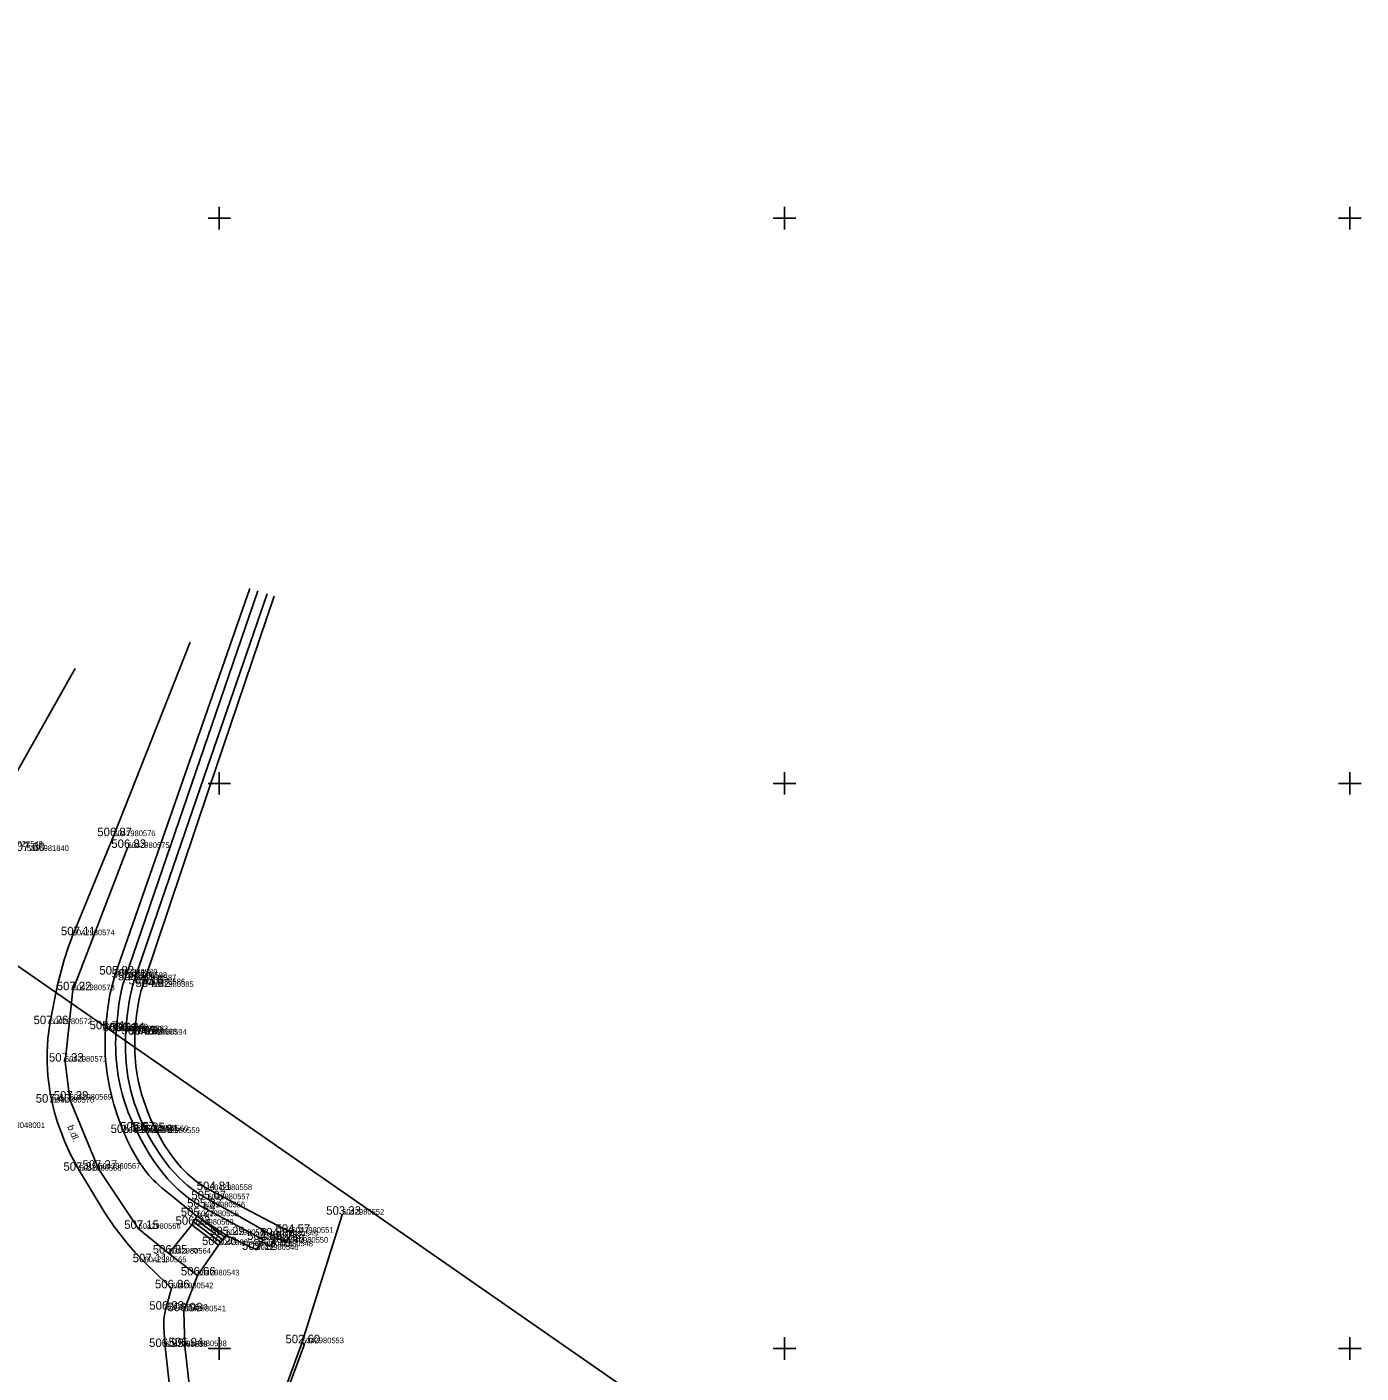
# Model space of a CAD drawing. Extents: x -669251 to -668549, y -1128351 to -1127698.
# Drawn here: x -668667 to -668549, y -1127952.2 to -1127833.1 of the extents above; entities that cross this region are included whole.
import ezdxf

# ---------------------------------------------------------------- set-up
doc = ezdxf.new("R2010")
doc.units = 0
for name, color, linetype in [('Vrstva 1', 7, 'Continuous'), ('Vrstva 10', 7, 'Continuous'), ('Vrstva 11', 7, 'Continuous'), ('Vrstva 2', 7, 'Continuous'), ('Vrstva 3', 7, 'Continuous'), ('Vrstva 40', 7, 'Continuous'), ('Vrstva 60', 7, 'Continuous'), ('Vrstva 61', 7, 'Continuous'), ('Vrstva 7', 7, 'Continuous'), ('Vrstva 9', 7, 'Continuous')]:
    doc.layers.add(name, color=color, linetype=linetype)

msp = doc.modelspace()

# ---------------------------------------------------------------- linework, layer by layer
at = {"layer": 'Vrstva 1'}
for p, q in [((-668659.36, -1127904.67), (-668659.36, -1127904.67)), ((-668658.12, -1127905.71), (-668658.12, -1127905.71)), ((-668662.97, -1127913.44), (-668662.97, -1127913.44)), ((-668659.2, -1127916.91), (-668659.2, -1127916.91)), ((-668658.34, -1127917.22), (-668658.34, -1127917.22)), ((-668657.52, -1127917.43), (-668657.52, -1127917.43)), ((-668656.74, -1127917.78), (-668656.74, -1127917.78)), ((-668655.99, -1127918.02), (-668655.99, -1127918.02)), ((-668662.97, -1127918.3), (-668662.97, -1127918.3)), ((-668664.99, -1127921.3), (-668664.99, -1127921.3)), ((-668660.06, -1127921.76), (-668660.06, -1127921.76)), ((-668659.12, -1127921.93), (-668659.12, -1127921.93)), ((-668658.26, -1127921.93), (-668658.26, -1127921.93)), ((-668657.46, -1127922.21), (-668657.46, -1127922.21)), ((-668656.6, -1127922.24), (-668656.6, -1127922.24)), ((-668663.65, -1127924.62), (-668663.65, -1127924.62)), ((-668664.79, -1127928.24), (-668664.79, -1127928.24)), ((-668663.23, -1127927.98), (-668663.23, -1127927.98)), ((-668658.42, -1127930.93), (-668658.42, -1127930.93)), ((-668657.34, -1127930.71), (-668657.34, -1127930.71)), ((-668656.47, -1127930.77), (-668656.47, -1127930.77)), ((-668655.45, -1127930.94), (-668655.45, -1127930.94)), ((-668662.37, -1127934.27), (-668662.37, -1127934.27)), ((-668660.7, -1127934.09), (-668660.7, -1127934.09)), ((-668651.03, -1127936.79), (-668651.03, -1127936.79)), ((-668650.82, -1127935.98), (-668650.82, -1127935.98)), ((-668651.43, -1127937.51), (-668651.43, -1127937.51)), ((-668639.13, -1127938.16), (-668639.13, -1127938.16)), ((-668657.14, -1127939.41), (-668657.14, -1127939.41)), ((-668652.44, -1127939.05), (-668652.44, -1127939.05)), ((-668651.99, -1127938.29), (-668651.99, -1127938.29)), ((-668649.4, -1127939.96), (-668649.4, -1127939.96)), ((-668646.12, -1127940.39), (-668646.12, -1127940.39)), ((-668644.99, -1127940.08), (-668644.99, -1127940.08)), ((-668644.08, -1127940.64), (-668644.08, -1127940.64)), ((-668643.61, -1127939.76), (-668643.61, -1127939.76)), ((-668654.46, -1127941.6), (-668654.46, -1127941.6)), ((-668650.07, -1127940.85), (-668650.07, -1127940.85)), ((-668646.72, -1127941.27), (-668646.72, -1127941.27)), ((-668645.43, -1127940.96), (-668645.43, -1127940.96)), ((-668656.62, -1127942.36), (-668656.62, -1127942.36)), ((-668651.94, -1127943.53), (-668651.94, -1127943.53)), ((-668654.24, -1127944.67), (-668654.24, -1127944.67)), ((-668654.76, -1127946.56), (-668654.76, -1127946.56)), ((-668653.13, -1127946.7), (-668653.13, -1127946.7)), ((-668654.78, -1127949.86), (-668654.78, -1127949.86)), ((-668653.06, -1127949.79), (-668653.06, -1127949.79)), ((-668642.69, -1127949.53), (-668642.69, -1127949.53))]:
    msp.add_line(p, q, dxfattribs=at)
at = {"layer": 'Vrstva 10'}
for p, q in [((-668662.74, -1127889.83), (-668682.21, -1127924.28)), ((-668651.94, -1127943.53), (-668654.46, -1127941.6)), ((-668645.91, -1127958.22), (-668642.69, -1127949.53)), ((-668645.66, -1127958.2), (-668642.45, -1127949.61)), ((-668642.69, -1127949.53), (-668642.45, -1127949.61))]:
    msp.add_line(p, q, dxfattribs=at)
for points in [[(-668654.24, -1127944.67), (-668655.43, -1127943.52), (-668656.62, -1127942.36), (-668657.48, -1127941.48), (-668658.19, -1127940.66), (-668659.33, -1127939.16), (-668660.13, -1127937.98), (-668661.26, -1127936.15), (-668662.37, -1127934.27), (-668663.16, -1127932.82), (-668663.67, -1127931.71), (-668664.3, -1127930.01), (-668664.57, -1127929.13), (-668664.79, -1127928.24), (-668664.96, -1127927.39), (-668665.17, -1127925.86), (-668665.24, -1127924.72), (-668665.24, -1127923.85), (-668665.17, -1127922.57), (-668664.99, -1127921.3), (-668664.62, -1127919.31), (-668664.3, -1127917.81), (-668663.72, -1127915.6), (-668663.37, -1127914.51), (-668662.97, -1127913.44), (-668661.16, -1127909.05), (-668659.36, -1127904.67), (-668655.98, -1127896.08), (-668652.59, -1127887.5)], [(-668651.54, -1127974.65), (-668652.61, -1127967.03), (-668653.68, -1127959.4), (-668654.27, -1127954.63), (-668654.78, -1127949.86), (-668654.92, -1127948.2), (-668654.9, -1127947.37), (-668654.76, -1127946.56), (-668654.5, -1127945.62), (-668654.24, -1127944.67)]]:
    msp.add_lwpolyline(points, dxfattribs=at)
at = {"layer": 'Vrstva 11'}
for p, q in [((-668652.44, -1127939.05), (-668650.07, -1127940.85)), ((-668652.28, -1127938.79), (-668649.9, -1127940.6)), ((-668652.13, -1127938.53), (-668649.73, -1127940.35)), ((-668651.99, -1127938.29), (-668651.76, -1127938.44)), ((-668651.76, -1127938.44), (-668649.56, -1127940.11)), ((-668651.76, -1127938.44), (-668649.4, -1127939.96))]:
    msp.add_line(p, q, dxfattribs=at)
at = {"layer": 'Vrstva 60'}
msp.add_lwpolyline([(-668788.58, -1128325.45), (-668557.46, -1127992.87), (-668787.38, -1127833.08), (-669018.51, -1128165.66)], close=True, dxfattribs=at)
at = {"layer": 'Vrstva 61'}
for p, q in [((-668651, -1127850), (-668649, -1127850)), ((-668650, -1127849), (-668650, -1127851)), ((-668601, -1127850), (-668599, -1127850)), ((-668600, -1127849), (-668600, -1127851)), ((-668551, -1127850), (-668549, -1127850)), ((-668550, -1127849), (-668550, -1127851)), ((-668651, -1127900), (-668649, -1127900)), ((-668650, -1127899), (-668650, -1127901)), ((-668601, -1127900), (-668599, -1127900)), ((-668600, -1127899), (-668600, -1127901)), ((-668551, -1127900), (-668549, -1127900)), ((-668550, -1127899), (-668550, -1127901)), ((-668651, -1127950), (-668649, -1127950)), ((-668650, -1127949), (-668650, -1127951)), ((-668601, -1127950), (-668599, -1127950)), ((-668600, -1127949), (-668600, -1127951)), ((-668551, -1127950), (-668549, -1127950)), ((-668550, -1127949), (-668550, -1127951))]:
    msp.add_line(p, q, dxfattribs=at)
at = {"layer": 'Vrstva 7'}
for p, q in [((-668642.69, -1127949.53), (-668639.13, -1127938.16)), ((-668646.72, -1127941.27), (-668649.4, -1127939.96)), ((-668646.24, -1127940.56), (-668646.72, -1127941.27)), ((-668646.12, -1127940.39), (-668646.24, -1127940.56)), ((-668646.24, -1127940.56), (-668645.43, -1127940.96)), ((-668645.43, -1127940.96), (-668645.02, -1127940.14)), ((-668645.02, -1127940.14), (-668644.08, -1127940.64)), ((-668643.61, -1127939.76), (-668644.08, -1127940.64))]:
    msp.add_line(p, q, dxfattribs=at)
for points in [[(-668651.99, -1127938.29), (-668653.53, -1127937.04), (-668655.07, -1127935.79), (-668655.35, -1127935.55), (-668655.6, -1127935.32), (-668655.83, -1127935.09), (-668656.23, -1127934.65), (-668656.56, -1127934.24), (-668656.83, -1127933.87), (-668657.06, -1127933.54), (-668657.25, -1127933.24), (-668657.57, -1127932.69), (-668657.79, -1127932.27), (-668658.11, -1127931.61), (-668658.42, -1127930.93), (-668658.65, -1127930.36), (-668658.86, -1127929.82), (-668659.04, -1127929.32), (-668659.19, -1127928.85), (-668659.33, -1127928.4), (-668659.55, -1127927.57), (-668659.72, -1127926.85), (-668659.84, -1127926.21), (-668659.93, -1127925.66), (-668659.99, -1127925.17), (-668660.04, -1127924.74), (-668660.09, -1127924), (-668660.11, -1127923.44), (-668660.1, -1127922.6), (-668660.09, -1127922.18), (-668660.06, -1127921.76), (-668660.01, -1127921.15), (-668659.89, -1127920.08), (-668659.78, -1127919.28), (-668659.67, -1127918.67), (-668659.57, -1127918.23), (-668659.4, -1127917.56), (-668659.2, -1127916.91), (-668653.26, -1127899.83), (-668647.31, -1127882.76)], [(-668646.6, -1127882.98), (-668652.47, -1127900.1), (-668658.34, -1127917.22), (-668658.52, -1127917.79), (-668658.65, -1127918.3), (-668658.74, -1127918.75), (-668658.88, -1127919.54), (-668658.96, -1127920.14), (-668659.05, -1127921.04), (-668659.12, -1127921.93), (-668659.15, -1127922.49), (-668659.17, -1127923), (-668659.16, -1127923.49), (-668659.15, -1127923.94), (-668659.12, -1127924.36), (-668659.04, -1127925.16), (-668658.94, -1127925.86), (-668658.83, -1127926.47), (-668658.71, -1127927), (-668658.59, -1127927.46), (-668658.47, -1127927.87), (-668658.24, -1127928.58), (-668658.05, -1127929.11), (-668657.89, -1127929.51), (-668657.63, -1127930.11), (-668657.34, -1127930.71), (-668657.07, -1127931.26), (-668656.8, -1127931.75), (-668656.54, -1127932.21), (-668656.29, -1127932.63), (-668656.05, -1127933.01), (-668655.82, -1127933.36), (-668655.36, -1127934), (-668654.95, -1127934.53), (-668654.57, -1127934.98), (-668654.22, -1127935.35), (-668653.91, -1127935.67), (-668653.63, -1127935.94), (-668653.12, -1127936.38), (-668652.72, -1127936.69), (-668652.41, -1127936.91), (-668651.93, -1127937.22), (-668651.43, -1127937.51), (-668648.77, -1127938.95), (-668646.12, -1127940.39)], [(-668645.02, -1127940.14), (-668648.01, -1127938.43), (-668651.03, -1127936.79), (-668651.47, -1127936.53), (-668651.87, -1127936.28), (-668652.23, -1127936.03), (-668652.55, -1127935.78), (-668652.85, -1127935.54), (-668653.12, -1127935.3), (-668653.62, -1127934.83), (-668654.03, -1127934.4), (-668654.38, -1127934), (-668654.67, -1127933.64), (-668654.92, -1127933.31), (-668655.33, -1127932.72), (-668655.63, -1127932.25), (-668655.85, -1127931.89), (-668656.17, -1127931.34), (-668656.47, -1127930.77), (-668656.74, -1127930.22), (-668656.97, -1127929.7), (-668657.17, -1127929.22), (-668657.34, -1127928.76), (-668657.49, -1127928.34), (-668657.61, -1127927.94), (-668657.82, -1127927.19), (-668657.97, -1127926.53), (-668658.08, -1127925.96), (-668658.15, -1127925.46), (-668658.21, -1127925.02), (-668658.27, -1127924.24), (-668658.3, -1127923.67), (-668658.3, -1127923.23), (-668658.29, -1127922.58), (-668658.26, -1127921.93), (-668658.17, -1127920.79), (-668658.07, -1127919.94), (-668657.98, -1127919.3), (-668657.89, -1127918.82), (-668657.81, -1127918.47), (-668657.68, -1127917.94), (-668657.52, -1127917.43), (-668651.65, -1127900.33), (-668645.78, -1127883.22)], [(-668645.16, -1127883.44), (-668650.95, -1127900.61), (-668656.74, -1127917.78), (-668656.91, -1127918.32), (-668657.03, -1127918.79), (-668657.12, -1127919.22), (-668657.24, -1127919.96), (-668657.32, -1127920.53), (-668657.4, -1127921.37), (-668657.46, -1127922.21), (-668657.48, -1127922.76), (-668657.48, -1127923.28), (-668657.47, -1127923.76), (-668657.45, -1127924.22), (-668657.41, -1127924.64), (-668657.37, -1127925.03), (-668657.26, -1127925.78), (-668657.14, -1127926.43), (-668657.01, -1127926.99), (-668656.87, -1127927.49), (-668656.74, -1127927.92), (-668656.48, -1127928.68), (-668656.26, -1127929.24), (-668656.08, -1127929.67), (-668655.78, -1127930.3), (-668655.45, -1127930.94), (-668655.23, -1127931.34), (-668655.02, -1127931.72), (-668654.81, -1127932.06), (-668654.4, -1127932.67), (-668654.03, -1127933.19), (-668653.69, -1127933.61), (-668653.38, -1127933.97), (-668653.09, -1127934.27), (-668652.84, -1127934.52), (-668652.61, -1127934.73), (-668652.2, -1127935.08), (-668651.87, -1127935.33), (-668651.62, -1127935.5), (-668651.23, -1127935.75), (-668650.82, -1127935.98), (-668647.22, -1127937.87), (-668643.61, -1127939.76)]]:
    msp.add_lwpolyline(points, dxfattribs=at)
at = {"layer": 'Vrstva 9'}
for p, q in [((-668662.97, -1127918.3), (-668658.12, -1127905.71)), ((-668663.65, -1127924.62), (-668662.97, -1127918.3)), ((-668663.23, -1127927.98), (-668663.65, -1127924.62)), ((-668660.7, -1127934.09), (-668663.23, -1127927.98)), ((-668657.14, -1127939.41), (-668660.7, -1127934.09)), ((-668654.46, -1127941.6), (-668657.14, -1127939.41)), ((-668654.46, -1127941.6), (-668652.44, -1127939.05)), ((-668652.44, -1127939.05), (-668651.99, -1127938.29)), ((-668649.4, -1127939.96), (-668650.07, -1127940.85)), ((-668650.07, -1127940.85), (-668651.94, -1127943.53)), ((-668653.13, -1127946.7), (-668651.94, -1127943.53)), ((-668653.06, -1127949.79), (-668653.13, -1127946.7)), ((-668652.65, -1127953.43), (-668653.06, -1127949.79))]:
    msp.add_line(p, q, dxfattribs=at)

# ---------------------------------------------------------------- texts
at = {"layer": 'Vrstva 2'}
for s, p in [('6042980576', (-668659.36, -1127904.67)), ('7851022549', (-668669.33, -1127905.6)), ('5866981840', (-668667.03, -1127905.98)), ('6042980575', (-668658.12, -1127905.71)), ('6042980574', (-668662.97, -1127913.44)), ('6042980589', (-668659.2, -1127916.91)), ('6042980588', (-668658.34, -1127917.22)), ('6042980573', (-668662.97, -1127918.3)), ('6042980587', (-668657.52, -1127917.43)), ('6042980586', (-668656.74, -1127917.78)), ('6042980585', (-668655.99, -1127918.02)), ('6042980572', (-668664.99, -1127921.3)), ('6042980590', (-668660.06, -1127921.76)), ('6042980591', (-668659.12, -1127921.93)), ('6042980592', (-668658.26, -1127921.93)), ('6042980593', (-668657.46, -1127922.21)), ('6042980594', (-668656.6, -1127922.24)), ('6042980571', (-668663.65, -1127924.62)), ('6042980569', (-668663.23, -1127927.98)), ('6042980570', (-668664.79, -1127928.24)), ('6043048001', (-668669.14, -1127930.49)), ('6042980562', (-668658.42, -1127930.93)), ('6042980561', (-668657.34, -1127930.71)), ('6042980560', (-668656.47, -1127930.77)), ('6042980559', (-668655.45, -1127930.94)), ('6042980568', (-668662.37, -1127934.27)), ('6042980567', (-668660.7, -1127934.09)), ('6042980558', (-668650.82, -1127935.98)), ('6042980556', (-668651.43, -1127937.51)), ('6042980557', (-668651.03, -1127936.79)), ('6042980555', (-668651.99, -1127938.29)), ('6042980552', (-668639.13, -1127938.16)), ('6042980566', (-668657.14, -1127939.41)), ('6042980563', (-668652.44, -1127939.05)), ('6042980545', (-668649.4, -1127939.96)), ('6042980551', (-668643.61, -1127939.76)), ('6042980544', (-668650.07, -1127940.85)), ('6042980547', (-668646.12, -1127940.39)), ('6042980548', (-668645.43, -1127940.96)), ('6042980549', (-668644.99, -1127940.08)), ('6042980550', (-668644.08, -1127940.64)), ('6042980564', (-668654.46, -1127941.6)), ('6042980546', (-668646.72, -1127941.27)), ('6042980565', (-668656.62, -1127942.36)), ('6042980543', (-668651.94, -1127943.53)), ('6042980542', (-668654.24, -1127944.67)), ('6042980540', (-668654.76, -1127946.56)), ('6042980541', (-668653.13, -1127946.7)), ('6042980539', (-668654.78, -1127949.86)), ('6042980538', (-668653.06, -1127949.79)), ('6042980553', (-668642.69, -1127949.53))]:
    msp.add_text(s, height=0.5, dxfattribs=at).set_placement(p)
at = {"layer": 'Vrstva 3'}
for s, p in [('506.87 ', (-668660.79, -1127904.67)), ('507.60 ', (-668668.5, -1127905.98)), ('506.83 ', (-668659.55, -1127905.71)), ('507.11 ', (-668664.01, -1127913.44)), ('505.82 ', (-668660.61, -1127916.91)), ('505.81 ', (-668659.52, -1127917.22)), ('505.50 ', (-668658.97, -1127917.43)), ('507.22 ', (-668664.38, -1127918.3)), ('505.16 ', (-668658.04, -1127917.78)), ('504.82 ', (-668657.41, -1127918.02)), ('507.26 ', (-668666.43, -1127921.3)), ('505.74 ', (-668661.47, -1127921.76)), ('505.61 ', (-668660.32, -1127921.93)), ('505.34 ', (-668659.67, -1127921.93)), ('505.01 ', (-668658.66, -1127922.21)), ('504.70 ', (-668658.05, -1127922.24)), ('507.33 ', (-668665.07, -1127924.62)), ('507.40 ', (-668666.24, -1127928.24)), ('507.39 ', (-668664.65, -1127927.98)), ('505.61 ', (-668659.61, -1127930.93)), ('505.57 ', (-668658.76, -1127930.71)), ('505.25 ', (-668657.89, -1127930.77)), ('504.91 ', (-668656.64, -1127930.94)), ('507.39 ', (-668663.79, -1127934.27)), ('507.37 ', (-668662.11, -1127934.09)), ('504.81 ', (-668652, -1127935.98)), ('505.37 ', (-668652.84, -1127937.51)), ('505.07 ', (-668652.47, -1127936.79)), ('505.27 ', (-668653.41, -1127938.29)), ('503.33 ', (-668640.54, -1127938.16)), ('507.15 ', (-668658.41, -1127939.41)), ('506.23 ', (-668653.87, -1127939.05)), ('505.29 ', (-668650.82, -1127939.96)), ('504.88 ', (-668646.41, -1127940.08)), ('504.57 ', (-668645.03, -1127939.76)), ('506.20 ', (-668651.53, -1127940.85)), ('505.12 ', (-668647.99, -1127941.27)), ('504.89 ', (-668647.54, -1127940.39)), ('504.81 ', (-668646.61, -1127940.96)), ('504.46 ', (-668645.52, -1127940.64)), ('507.11 ', (-668657.66, -1127942.36)), ('506.85 ', (-668655.89, -1127941.6)), ('506.66 ', (-668653.4, -1127943.53)), ('506.86 ', (-668655.69, -1127944.67)), ('506.93 ', (-668656.19, -1127946.56)), ('506.96 ', (-668654.59, -1127946.7)), ('502.60 ', (-668644.15, -1127949.53)), ('506.99 ', (-668656.21, -1127949.86)), ('506.94 ', (-668654.49, -1127949.79))]:
    msp.add_text(s, height=0.75, dxfattribs=at).set_placement(p)
at = {"layer": 'Vrstva 40'}
for s, rotation, p in [('b.dl.', 292.2713, (-668663.46, -1127930.37)), ('b.', 55.163, (-668652.1, -1127941.63))]:
    msp.add_text(s, height=0.6, rotation=rotation, dxfattribs=at).set_placement(p)

doc.saveas('drawing.dxf')
